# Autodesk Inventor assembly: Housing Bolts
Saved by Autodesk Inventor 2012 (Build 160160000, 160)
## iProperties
Created: 2011-01
Part Number: Housing Bolts
Document SubType Name: Assembly
Designer: Beta-8540w
ClientObjectVersion: 1
Author: Beta-8540w
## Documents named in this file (3)
- C:\Users\VMuser\Desktop\Inventor 2012 Essentials\Assemblies\Chapter 8\Design Accelerators\Bolted Connection c8-01.iam
- C:\Users\VMuser\Desktop\Inventor 2012 Essentials\Content Center Files\en-US\ISO 7089\ISO 7089 - 4 - 140 HV.ipt
- C:\Users\VMuser\Desktop\Inventor 2012 Essentials\Content Center Files\en-US\ISO 4762\ISO 4762 - M4 x 10ISO.ipt
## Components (16 placed, 2 different names)
1. ISO 7089 4 - 140 HV:1
2. ISO 4762 M4 x 10:1
3. ISO 4762 M4 x 10:2
4. ISO 4762 M4 x 10:3
5. ISO 4762 M4 x 10:4
6. ISO 4762 M4 x 10:5
7. ISO 4762 M4 x 10:6
8. ISO 4762 M4 x 10:7
9. ISO 4762 M4 x 10:8
10. ISO 7089 4 - 140 HV:2
11. ISO 7089 4 - 140 HV:3
12. ISO 7089 4 - 140 HV:4
13. ISO 7089 4 - 140 HV:5
14. ISO 7089 4 - 140 HV:6
15. ISO 7089 4 - 140 HV:7
16. ISO 7089 4 - 140 HV:8
